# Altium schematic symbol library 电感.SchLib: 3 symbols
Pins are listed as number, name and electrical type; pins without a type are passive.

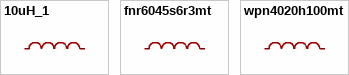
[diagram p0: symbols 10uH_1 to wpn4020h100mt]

## 10uH_1
designator L??  (value not drawn)
footprint BAT-SMD_2P-P2.54_2P-2.54PH-7.0H
pins: 1, 2

## fnr6045s6r3mt
designator L??  (value not drawn)
电感值:6.3uH;精度:±20%;额定电流:3.3A;饱和电流(Isat):4.7A;类型:磁胶屏蔽绕线合金电感;; Manufacturer: cjiang(长江微电); AddInBom: yes; ModelId: a3b1a14981914683918d1fd1319c5d5c; ModelName: IND-SMD_L6.0-W6.0-H2.8; ModelTransform: 236.22,237.007,0,90,0,0,0,0,0; Value: 6.3uH; Tolerance: ±20%; Current Rating: 3.3A; Current - Saturation(Isat): 4.7A; DC Resistance(DCR): 40mΩ
footprint IND-SMD_L6.0-W6.0_FNR60XXS
pins: 1, 2

## wpn4020h100mt
designator L??  (value not drawn)
电感值:10uH;精度:±20%;额定电流:2A;饱和电流(Isat):3.5A;类型:-;; Manufacturer: Sunlord(顺络); AddInBom: yes; ModelId: 45bc3737ecfd4f3bb122605ee525b018; ModelName: IND-SMD_L4.0-W4.0-H1.9; ModelTransform: 157.48,157.484,0,0,0,0,0,0,0; Value: 10uH; Tolerance: ±20%; Current Rating: 2A; Current - Saturation(Isat): 3.5A; DC Resistance(DCR): 216mΩ
footprint IND-SMD_L4.0-W4.0
pins: 1, 2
